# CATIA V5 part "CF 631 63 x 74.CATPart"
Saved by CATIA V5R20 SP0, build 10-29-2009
Part number: CF 631 63 x 74
Definition: NONE
Nomenclature: CF 631 63 x 74
Source: Unknown
Description: CF 631 63 x 74
Bounding box of the stored display mesh (mm): x -13 to 61, y -46 to 46, z -46 to 46
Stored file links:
  C:\Users\Utente\Desktop\IO LAVORO\3D X SITO CF\X SITO\CF 631\CF 631 63 x 74.CATPart
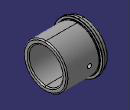
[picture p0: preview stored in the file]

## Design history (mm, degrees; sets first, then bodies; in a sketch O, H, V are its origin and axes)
Body1 "CF 631 63 x 74" (main body)
  Solid1: solid without history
